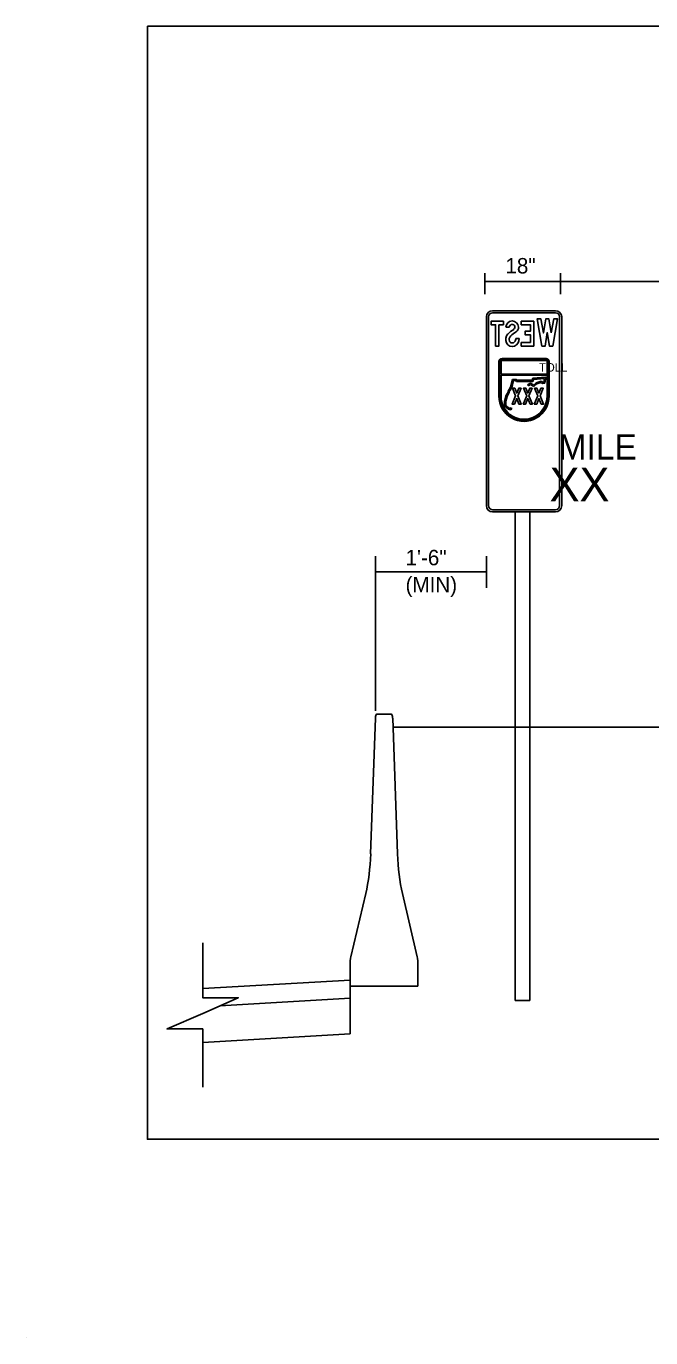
# Model space of a CAD drawing. Extents: x 57428 to 58066, y 11696 to 12105.
# Drawn here: x 57427.9 to 57541.3, y 11696.3 to 11934.3 of the extents above; entities that cross this region are included whole.
import ezdxf

# ---------------------------------------------------------------- set-up
doc = ezdxf.new("R2010")
doc.units = 0
for name, color, linetype in [('AdhocPoint_dp', 7, 'Continuous'), ('Default', 7, 'Continuous'), ('DimLines_dp', 7, 'Continuous'), ('NonPlottingEle_dp', 7, 'Continuous'), ('SignPanel', 7, 'Continuous'), ('TextMisc', 7, 'Continuous'), ('XSGrdLine_ex', 7, 'Continuous')]:
    doc.layers.add(name, color=color, linetype=linetype)

msp = doc.modelspace()

# ---------------------------------------------------------------- linework, layer by layer
at = {"layer": 'AdhocPoint_dp'}
msp.add_line((57427.89, 11696.32), (57427.89, 11696.32), dxfattribs=at)
at = {"layer": 'Default'}
msp.add_lwpolyline([(57459.93, 11741.8), (57459.93, 11752.36), (57453.47, 11752.36), (57459.93, 11755.17), (57466.39, 11757.99), (57459.93, 11757.99), (57459.93, 11767.99)], dxfattribs=at)
at = {"layer": 'DimLines_dp'}
for p, q in [((57511.19, 11885.65), (57511.19, 11889.48)), ((57511.19, 11887.93), (57524.88, 11887.93)), ((57524.88, 11885.65), (57524.88, 11889.48)), ((57524.88, 11887.93), (57585.54, 11887.93)), ((57491.3, 11810.03), (57491.3, 11838.14)), ((57511.44, 11832.39), (57511.44, 11838.14)), ((57491.3, 11835.3), (57511.44, 11835.3))]:
    msp.add_line(p, q, dxfattribs=at)
at = {"layer": 'NonPlottingEle_dp'}
for p, q in [((57516.7, 11807.11), (57516.7, 11846.15)), ((57519.36, 11807.11), (57519.36, 11846.15)), ((57516.7, 11757.53), (57516.7, 11807.11)), ((57519.36, 11757.53), (57519.36, 11807.11)), ((57516.7, 11757.53), (57519.36, 11757.53))]:
    msp.add_line(p, q, dxfattribs=at)
at = {"layer": 'SignPanel'}
for p, q in [((57515.59, 11879.64), (57514.97, 11879.64)), ((57515.59, 11879.64), (57514.97, 11879.64)), ((57515.59, 11879.64), (57514.97, 11879.64)), ((57516.78, 11877.63), (57517.41, 11877.63)), ((57516.78, 11877.63), (57517.41, 11877.63)), ((57516.78, 11877.63), (57517.41, 11877.63)), ((57513.72, 11867.13), (57513.72, 11873.41)), ((57513.91, 11867.13), (57513.91, 11873.41)), ((57514.1, 11871.13), (57514.1, 11873.41)), ((57522.27, 11873.98), (57514.29, 11873.98)), ((57522.27, 11873.79), (57514.29, 11873.79)), ((57522.27, 11873.6), (57514.29, 11873.6)), ((57522.47, 11871.13), (57522.47, 11873.41)), ((57522.65, 11867.13), (57522.65, 11873.41)), ((57522.84, 11867.13), (57522.84, 11873.41)), ((57522.47, 11871.13), (57514.1, 11871.13)), ((57514.1, 11867.13), (57514.1, 11870.94)), ((57522.47, 11870.94), (57514.1, 11870.94)), ((57522.47, 11867.13), (57522.47, 11870.94)), ((57515.84, 11868.76), (57515.38, 11868.04)), ((57515.61, 11867.97), (57516.05, 11868.67)), ((57516.17, 11870.19), (57515.84, 11868.76)), ((57516.05, 11868.67), (57516.35, 11869.97)), ((57516.9, 11870.19), (57516.17, 11870.19)), ((57516.35, 11869.97), (57516.78, 11869.97)), ((57516.78, 11869.97), (57516.89, 11869.81)), ((57516.89, 11869.81), (57519.89, 11869.81)), ((57517.01, 11870.04), (57516.9, 11870.19)), ((57519.74, 11870.04), (57517.01, 11870.04)), ((57519.44, 11869.52), (57518.94, 11869.18)), ((57518.94, 11869.18), (57519.07, 11868.99)), ((57519.07, 11868.99), (57519.45, 11869.25)), ((57520.05, 11869.16), (57519.44, 11869.52)), ((57519.45, 11869.25), (57520.08, 11868.88)), ((57519.87, 11870.39), (57519.74, 11870.04)), ((57522.25, 11870.57), (57519.87, 11870.39)), ((57519.89, 11869.81), (57520.03, 11870.17)), ((57520.03, 11870.17), (57521.98, 11870.32)), ((57520.5, 11869.58), (57520.05, 11869.16)), ((57520.08, 11868.88), (57520.62, 11869.37)), ((57521.42, 11869.88), (57520.5, 11869.58)), ((57520.62, 11869.37), (57521.38, 11869.62)), ((57520.99, 11870.23), (57520.99, 11870.23)), ((57521.38, 11869.62), (57521.63, 11869.42)), ((57521.69, 11869.66), (57521.42, 11869.88)), ((57521.63, 11869.42), (57522.08, 11869.48)), ((57521.88, 11869.69), (57521.69, 11869.66)), ((57521.98, 11870.32), (57521.88, 11869.69)), ((57522.08, 11869.48), (57522.25, 11870.57)), ((57514.97, 11867.18), (57514.72, 11866.26)), ((57514.72, 11866.26), (57514.72, 11865.39)), ((57514.95, 11866.23), (57515.19, 11867.09)), ((57514.95, 11865.5), (57514.95, 11866.23)), ((57515.38, 11867.85), (57514.97, 11867.18)), ((57515.19, 11867.09), (57515.61, 11867.79)), ((57515.38, 11868.04), (57515.38, 11867.85)), ((57515.61, 11867.79), (57515.61, 11867.97)), ((57514.72, 11865.39), (57515.47, 11864.78)), ((57515.58, 11864.99), (57514.95, 11865.5)), ((57515.47, 11864.78), (57515.83, 11864.69)), ((57515.79, 11864.94), (57515.58, 11864.99)), ((57515.93, 11865.04), (57515.79, 11864.94)), ((57515.83, 11864.69), (57516.06, 11864.85)), ((57516.06, 11864.85), (57515.93, 11865.04))]:
    msp.add_line(p, q, dxfattribs=at)
for points in [[(57523.99, 11882.65), (57512.58, 11882.65)], [(57511.44, 11881.51), (57511.44, 11847.29)], [(57511.82, 11881.51), (57511.82, 11847.29)], [(57523.99, 11882.27), (57512.58, 11882.27)], [(57524.75, 11847.29), (57524.75, 11881.51)], [(57525.13, 11847.29), (57525.13, 11881.51)], [(57512.58, 11846.53), (57523.99, 11846.53)], [(57512.58, 11846.15), (57523.99, 11846.15)]]:
    msp.add_lwpolyline(points, dxfattribs=at)
for points in [[(57513.73, 11880.09), (57514.55, 11880.09), (57514.55, 11880.72), (57512.29, 11880.72), (57512.29, 11880.09), (57513.11, 11880.09), (57513.11, 11876.22), (57513.73, 11876.22)], [(57513.73, 11880.09), (57514.55, 11880.09), (57514.55, 11880.72), (57512.29, 11880.72), (57512.29, 11880.09), (57513.11, 11880.09), (57513.11, 11876.22), (57513.73, 11876.22)], [(57513.73, 11880.09), (57514.55, 11880.09), (57514.55, 11880.72), (57512.29, 11880.72), (57512.29, 11880.09), (57513.11, 11880.09), (57513.11, 11876.22), (57513.73, 11876.22)], [(57519.44, 11876.85), (57519.44, 11878.29), (57518.46, 11878.29), (57518.46, 11878.92), (57519.44, 11878.92), (57519.44, 11880.09), (57517.79, 11880.09), (57517.79, 11880.72), (57520.06, 11880.72), (57520.06, 11876.22), (57517.79, 11876.22), (57517.79, 11876.85)], [(57519.44, 11876.85), (57519.44, 11878.29), (57518.46, 11878.29), (57518.46, 11878.92), (57519.44, 11878.92), (57519.44, 11880.09), (57517.79, 11880.09), (57517.79, 11880.72), (57520.06, 11880.72), (57520.06, 11876.22), (57517.79, 11876.22), (57517.79, 11876.85)], [(57519.44, 11876.85), (57519.44, 11878.29), (57518.46, 11878.29), (57518.46, 11878.92), (57519.44, 11878.92), (57519.44, 11880.09), (57517.79, 11880.09), (57517.79, 11880.72), (57520.06, 11880.72), (57520.06, 11876.22), (57517.79, 11876.22), (57517.79, 11876.85)], [(57523.22, 11878.61), (57522.81, 11881.17), (57522.21, 11881.17), (57521.81, 11878.61), (57521.35, 11881.17), (57520.66, 11881.17), (57521.54, 11876.22), (57522.12, 11876.22), (57522.51, 11878.69), (57522.9, 11876.22), (57523.49, 11876.22), (57524.37, 11881.17), (57523.67, 11881.17)], [(57523.22, 11878.61), (57522.81, 11881.17), (57522.21, 11881.17), (57521.81, 11878.61), (57521.35, 11881.17), (57520.66, 11881.17), (57521.54, 11876.22), (57522.12, 11876.22), (57522.51, 11878.69), (57522.9, 11876.22), (57523.49, 11876.22), (57524.37, 11881.17), (57523.67, 11881.17)], [(57523.22, 11878.61), (57522.81, 11881.17), (57522.21, 11881.17), (57521.81, 11878.61), (57521.35, 11881.17), (57520.66, 11881.17), (57521.54, 11876.22), (57522.12, 11876.22), (57522.51, 11878.69), (57522.9, 11876.22), (57523.49, 11876.22), (57524.37, 11881.17), (57523.67, 11881.17)], [(57517.36, 11865.71), (57516.95, 11866.69), (57516.55, 11865.71), (57516.12, 11865.71), (57516.74, 11867.2), (57516.17, 11868.57), (57516.6, 11868.57), (57516.95, 11867.71), (57517.31, 11868.57), (57517.74, 11868.57), (57517.17, 11867.2), (57517.79, 11865.71)], [(57519.38, 11865.71), (57518.97, 11866.69), (57518.56, 11865.71), (57518.13, 11865.71), (57518.76, 11867.2), (57518.18, 11868.57), (57518.61, 11868.57), (57518.97, 11867.71), (57519.33, 11868.57), (57519.75, 11868.57), (57519.18, 11867.2), (57519.8, 11865.71)], [(57521.39, 11865.71), (57520.99, 11866.69), (57520.58, 11865.71), (57520.15, 11865.71), (57520.77, 11867.2), (57520.2, 11868.57), (57520.63, 11868.57), (57520.99, 11867.71), (57521.34, 11868.57), (57521.77, 11868.57), (57521.2, 11867.2), (57521.82, 11865.71)]]:
    msp.add_lwpolyline(points, close=True, dxfattribs=at)
for centre, radius, start, end in [((57512.58, 11881.51), 1.14, 90, 180), ((57523.99, 11881.51), 1.14, 0, 90), ((57512.58, 11881.51), 0.76, 90, 180), ((57523.99, 11881.51), 0.76, 0, 90), ((57512.58, 11847.29), 1.14, 180, 270), ((57512.58, 11847.29), 0.76, 180, 270), ((57523.99, 11847.29), 1.14, 270, 0), ((57523.99, 11847.29), 0.76, 270, 0)]:
    msp.add_arc(centre, radius, start, end, dxfattribs=at)
for centre, major_axis, ratio, start_param, end_param in [((57516.12, 11879.61), (0, -1.17), 0.981197, 1.634182, 4.688511), ((57516.12, 11879.61), (0, -1.17), 0.981197, 1.634182, 4.688511), ((57516.12, 11879.61), (0, -1.17), 0.981197, 1.634182, 4.688511), ((57516.32, 11877.45), (0, -1.4), 0.981197, 3.939023, 5.163791), ((57516.32, 11877.45), (0, -1.4), 0.981197, 3.939023, 5.163791), ((57516.32, 11877.45), (0, -1.4), 0.981197, 3.939023, 5.163791), ((57518.44, 11875.47), (0, -4.32), 0.981197, 3.642536, 3.961892), ((57518.44, 11875.47), (0, -4.32), 0.981197, 3.642536, 3.961892), ((57518.44, 11875.47), (0, -4.32), 0.981197, 3.642536, 3.961892), ((57516.33, 11877.45), (0, -0.78), 0.981197, 3.79238, 5.170369), ((57516.33, 11877.45), (0, -0.78), 0.981197, 3.79238, 5.170369), ((57516.33, 11877.45), (0, -0.78), 0.981197, 3.79238, 5.170369), ((57516.13, 11879.6), (0, -0.55), 0.981197, 2.28404, 4.637874), ((57516.13, 11879.6), (0, -0.55), 0.981197, 2.28404, 4.637874), ((57516.13, 11879.6), (0, -0.55), 0.981197, 2.28404, 4.637874), ((57518.97, 11874.79), (0, -4.56), 0.981197, 3.63779, 3.909641), ((57518.97, 11874.79), (0, -4.56), 0.981197, 3.63779, 3.909641), ((57518.97, 11874.79), (0, -4.56), 0.981197, 3.63779, 3.909641), ((57516.19, 11879.67), (0, -0.453), 0.981197, 0.484634, 2.267813), ((57516.19, 11879.67), (0, -0.453), 0.981197, 0.484634, 2.267813), ((57516.19, 11879.67), (0, -0.453), 0.981197, 0.484634, 2.267813), ((57516.24, 11879.65), (0, -1.05), 0.981197, 0.629826, 1.606762), ((57516.24, 11879.65), (0, -1.05), 0.981197, 0.629826, 1.606762), ((57516.24, 11879.65), (0, -1.05), 0.981197, 0.629826, 1.606762), ((57516.16, 11877.38), (0, -1.23), 0.981197, 5.173086, 6.638731), ((57516.16, 11877.38), (0, -1.23), 0.981197, 5.173086, 6.638731), ((57516.16, 11877.38), (0, -1.23), 0.981197, 5.173086, 6.638731), ((57516.14, 11877.37), (0, -0.572), 0.981197, 5.194718, 7.162991), ((57516.14, 11877.37), (0, -0.572), 0.981197, 5.194718, 7.162991), ((57516.14, 11877.37), (0, -0.572), 0.981197, 5.194718, 7.162991), ((57515.9, 11877.59), (0, -0.897), 0.981197, 0.859453, 1.616836), ((57515.9, 11877.59), (0, -0.897), 0.981197, 0.859453, 1.616836), ((57515.9, 11877.59), (0, -0.897), 0.981197, 0.859453, 1.616836), ((57515.96, 11877.56), (0, -1.47), 0.981197, 0.439911, 1.615229), ((57515.96, 11877.56), (0, -1.47), 0.981197, 0.439911, 1.615229), ((57515.96, 11877.56), (0, -1.47), 0.981197, 0.439911, 1.615229), ((57514.29, 11873.41), (0, 0.57), 0.9997, 0, 1.570796), ((57514.29, 11873.41), (0, 0.38), 0.9997, 0, 1.570796), ((57514.29, 11873.41), (0, 0.19), 0.9997, 0, 1.570796), ((57522.27, 11873.41), (0, 0.57), 0.9997, 4.712389, 6.283185), ((57522.27, 11873.41), (0, 0.38), 0.9997, 4.712389, 6.283185), ((57522.27, 11873.41), (0, 0.19), 0.9997, 4.712389, 6.283185), ((57518.28, 11867.13), (0, 4.56), 0.9997, 1.570796, 4.712389), ((57518.28, 11867.13), (0, 4.37), 0.9997, 1.570796, 4.712389), ((57518.28, 11867.13), (0, 4.18), 0.9997, 1.570796, 4.712389)]:
    msp.add_ellipse(centre, major_axis=major_axis, ratio=ratio, start_param=start_param, end_param=end_param, dxfattribs=at)
at = {"layer": 'TextMisc'}
msp.add_lwpolyline([(57449.89, 11934.25), (57709.55, 11934.25), (57709.55, 11732.32), (57449.89, 11732.32)], close=True, dxfattribs=at)
at = {"layer": 'XSGrdLine_ex'}
for p, q in [((57494.17, 11809.43), (57491.55, 11809.43)), ((57490.43, 11784.12), (57491.3, 11808.74)), ((57495.29, 11784.12), (57494.43, 11808.74)), ((57494.48, 11807.11), (57616.18, 11807.11)), ((57486.86, 11765.45), (57489.53, 11776.9)), ((57498.86, 11765.45), (57496.19, 11776.9)), ((57486.7, 11760.13), (57486.7, 11763.91)), ((57499.02, 11760.13), (57499.02, 11763.91)), ((57459.93, 11759.71), (57486.7, 11761.2)), ((57486.7, 11761.2), (57486.7, 11760.13)), ((57499.02, 11760.13), (57486.7, 11760.13)), ((57486.7, 11760.13), (57486.7, 11751.48)), ((57486.7, 11757.95), (57463.05, 11756.53)), ((57486.7, 11751.48), (57459.93, 11749.87))]:
    msp.add_line(p, q, dxfattribs=at)
for centre, major_axis, start_param, end_param in [((57491.55, 11808.66), (0, 0.77), 0, 1.465919), ((57494.17, 11808.66), (0, 0.77), 4.817266, 6.283185), ((57485.33, 11785.73), (0, -15.4), 0.96007, 1.465919), ((57500.4, 11785.73), (0, -15.4), 4.817266, 5.323115), ((57487.6, 11763.91), (0, 2.7), 0.96007, 1.570796), ((57498.12, 11763.91), (0, 2.7), 4.712389, 5.323115)]:
    msp.add_ellipse(centre, major_axis=major_axis, ratio=0.333333, start_param=start_param, end_param=end_param, dxfattribs=at)

# ---------------------------------------------------------------- texts
at = {"layer": 'DimLines_dp'}
for s, p in [('18"', (57514.9, 11889.4)), ('1\'-6"', (57496.77, 11836.46)), ('(MIN)', (57496.77, 11831.56))]:
    msp.add_text(s, height=2.8, dxfattribs=at).set_placement(p)
at = {"layer": 'SignPanel'}
for s, height, p in [('TOLL', 1.519, (57521.04, 11871.6)), ('MILE', 4.562, (57524.54, 11855.65)), ('XX', 6.083, (57522.93, 11848.08))]:
    msp.add_text(s, height=height, dxfattribs=at).set_placement(p)

doc.saveas('drawing.dxf')
